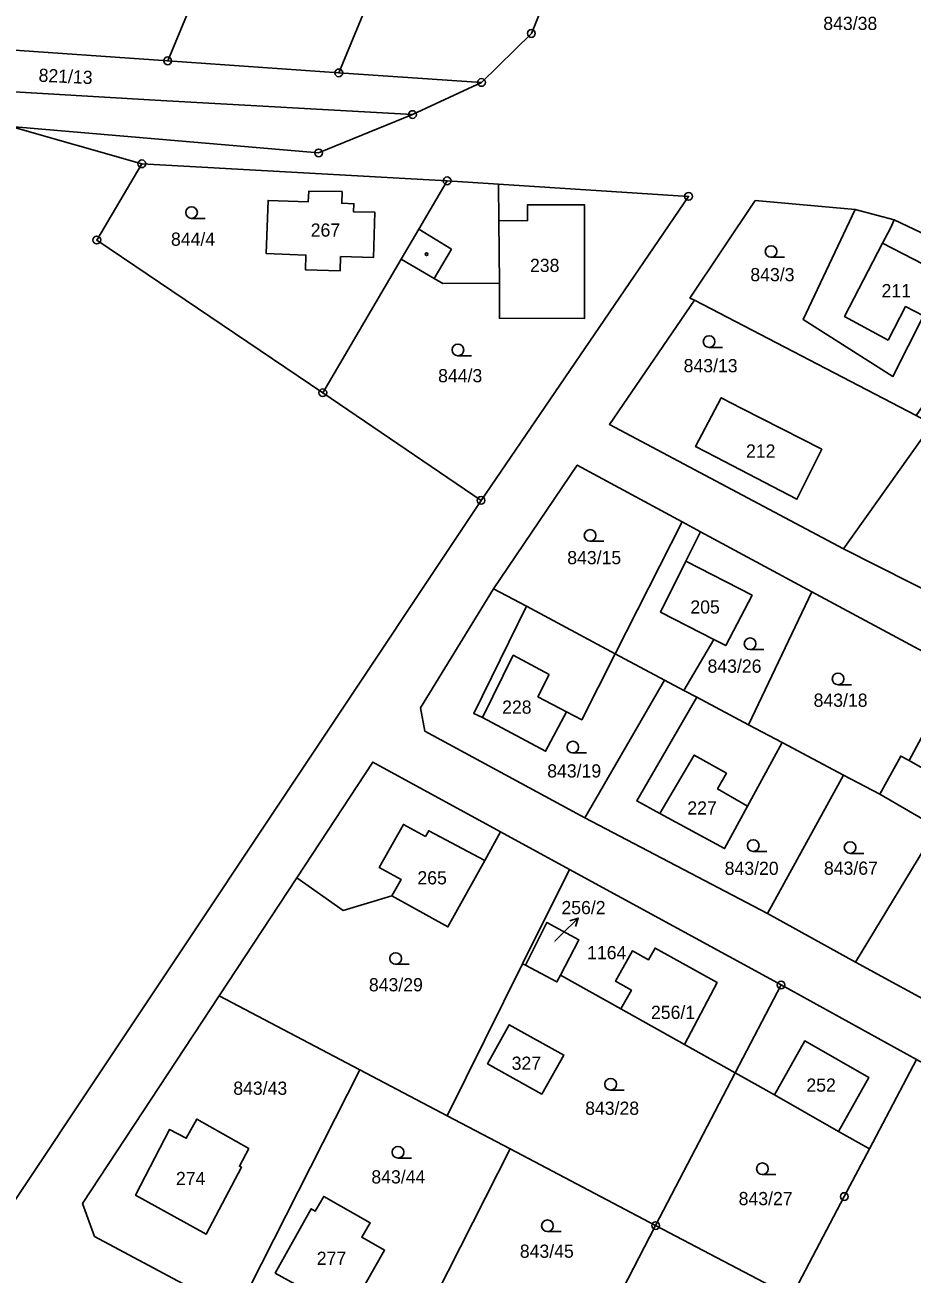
# Model space of a CAD drawing. Extents: x -654083 to -650132, y -1099819 to -1096699.
# Drawn here: x -652566 to -652451.7, y -1098294.4 to -1098133.4 of the extents above; entities that cross this region are included whole.
import ezdxf

# ---------------------------------------------------------------- set-up
doc = ezdxf.new("R2010")
doc.units = 0
for name, color, linetype in [('Geodetické body', 7, 'Continuous'), ('Hranice - vnitř_ kresba', 7, 'Continuous'), ('Obvody jako plochy', 7, 'Continuous'), ('Parcelní čísla', 7, 'Continuous'), ('Prvky pro prodl_ par_ č_', 7, 'Continuous'), ('Značky kultur', 7, 'Continuous'), ('Značky na budově ne v SPI', 7, 'Continuous')]:
    doc.layers.add(name, color=color, linetype=linetype)

msp = doc.modelspace()

# ---------------------------------------------------------------- linework, layer by layer
at = {"layer": 'Geodetické body'}
for centre, radius in [((-652500.78, -1098134.52), 0.5), ((-652500.78, -1098134.52), 0.001), ((-652547.65, -1098138.05), 0.5), ((-652547.65, -1098138.05), 0.001), ((-652525.6, -1098139.6), 0.5), ((-652525.6, -1098139.6), 0.001), ((-652507.21, -1098140.83), 0.5), ((-652507.21, -1098140.83), 0.001), ((-652516.1, -1098144.97), 0.5), ((-652516.1, -1098144.97), 0.001), ((-652550.98, -1098151.31), 0.5), ((-652528.2, -1098149.91), 0.5), ((-652528.2, -1098149.91), 0.001), ((-652550.98, -1098151.31), 0.001), ((-652511.64, -1098153.51), 0.5), ((-652511.64, -1098153.51), 0.001), ((-652480.53, -1098155.51), 0.5), ((-652480.53, -1098155.51), 0.001), ((-652556.79, -1098161.13), 0.5), ((-652556.79, -1098161.13), 0.001), ((-652527.66, -1098180.81), 0.5), ((-652527.66, -1098180.81), 0.001), ((-652507.27, -1098194.68), 0.5), ((-652507.27, -1098194.68), 0.001), ((-652468.6, -1098257.11), 0.5), ((-652468.6, -1098257.11), 0.001), ((-652460.45, -1098284.37), 0.5), ((-652460.45, -1098284.37), 0.001), ((-652484.77, -1098288.11), 0.5), ((-652484.77, -1098288.11), 0.001)]:
    msp.add_circle(centre, radius, dxfattribs=at)
at = {"layer": 'Hranice - vnitř_ kresba'}
for p, q in [((-652504.9, -1098166.67), (-652504.99, -1098158.68)), ((-652511.08, -1098162.29), (-652515.3, -1098159.74)), ((-652455.52, -1098161.54), (-652460.42, -1098170.99)), ((-652513.3, -1098166.11), (-652511.08, -1098162.29)), ((-652454.8, -1098174.04), (-652452.55, -1098169.7)), ((-652452.55, -1098169.7), (-652450.26, -1098170.9)), ((-652460.42, -1098170.99), (-652454.8, -1098174.04)), ((-652480.87, -1098202.52), (-652484.13, -1098209.06)), ((-652484.13, -1098209.06), (-652477.28, -1098212.58)), ((-652507.09, -1098222.64), (-652503.11, -1098214.64)), ((-652503.11, -1098214.64), (-652498.49, -1098217.11)), ((-652498.49, -1098217.11), (-652499.94, -1098219.98)), ((-652496.24, -1098221.91), (-652499.94, -1098219.98)), ((-652484.24, -1098235), (-652479.8, -1098227.5)), ((-652479.8, -1098227.5), (-652475.65, -1098229.83)), ((-652447.46, -1098230.86), (-652452.11, -1098228.21)), ((-652475.65, -1098229.83), (-652476.79, -1098231.86)), ((-652476.79, -1098231.86), (-652472.93, -1098234.09)), ((-652517.27, -1098236.42), (-652520.39, -1098241.96)), ((-652514.44, -1098238), (-652517.27, -1098236.42)), ((-652514.44, -1098238), (-652514.01, -1098237.24)), ((-652514.01, -1098237.24), (-652506.79, -1098241.06)), ((-652520.39, -1098241.96), (-652517.58, -1098243.51)), ((-652518.77, -1098245.61), (-652517.58, -1098243.51)), ((-652469.47, -1098271.27), (-652465.55, -1098264.32)), ((-652465.55, -1098264.32), (-652457.29, -1098269.05)), ((-652457.29, -1098269.05), (-652461.18, -1098275.97))]:
    msp.add_line(p, q, dxfattribs=at)
at = {"layer": 'Obvody jako plochy'}
for points in [[(-652547.65, -1098138.05), (-652531.11, -1098098.13), (-652538.85, -1098095.14), (-652538.06, -1098093.13), (-652551.9, -1098093.63), (-652569.89, -1098136.49)], [(-652511.58, -1098105.71), (-652525.6, -1098139.6), (-652547.65, -1098138.05), (-652531.11, -1098098.13)], [(-652507.21, -1098140.83), (-652500.78, -1098134.52), (-652498.91, -1098129.94), (-652495.32, -1098121.29), (-652492.02, -1098113.3), (-652511.58, -1098105.71), (-652525.6, -1098139.6)], [(-652507.27, -1098194.68), (-652527.66, -1098180.81), (-652556.79, -1098161.13), (-652550.98, -1098151.31), (-652567.88, -1098146.52), (-652571.82, -1098152.16), (-652589.48, -1098177.59), (-652601.2, -1098194.45), (-652613.08, -1098211.55), (-652624.95, -1098228.23), (-652628.47, -1098233.23), (-652636.96, -1098245.34), (-652638.2, -1098247.18), (-652572.57, -1098292.6)], [(-652527.66, -1098180.81), (-652517.57, -1098163.62), (-652515.3, -1098159.74), (-652511.64, -1098153.51), (-652550.98, -1098151.31), (-652556.79, -1098161.13)], [(-652513.3, -1098166.11), (-652517.57, -1098163.62), (-652527.66, -1098180.81), (-652507.27, -1098194.68), (-652480.53, -1098155.51), (-652505.04, -1098153.93), (-652504.99, -1098158.68), (-652501.26, -1098158.62), (-652501.26, -1098156.58), (-652493.93, -1098156.61), (-652493.95, -1098171.25), (-652504.89, -1098171.22), (-652504.9, -1098166.67), (-652512.2, -1098166.75)], [(-652511.64, -1098153.51), (-652505.04, -1098153.93), (-652504.99, -1098158.68), (-652501.26, -1098158.62), (-652501.26, -1098156.58), (-652493.93, -1098156.61), (-652493.95, -1098171.25), (-652504.89, -1098171.22), (-652504.9, -1098166.67), (-652512.2, -1098166.75), (-652513.3, -1098166.11), (-652517.57, -1098163.62), (-652515.3, -1098159.74)], [(-652525.17, -1098154.89), (-652529.46, -1098154.83), (-652529.56, -1098156.23), (-652534.72, -1098156.04), (-652534.98, -1098162.86), (-652529.83, -1098163.07), (-652529.9, -1098164.96), (-652525.41, -1098165.1), (-652525.36, -1098163.26), (-652521.13, -1098163.39), (-652520.95, -1098157.55), (-652523.7, -1098157.52), (-652523.65, -1098156.45), (-652525.21, -1098156.39)], [(-652534.72, -1098156.04), (-652534.98, -1098162.86), (-652529.83, -1098163.07), (-652529.9, -1098164.96), (-652525.41, -1098165.1), (-652525.36, -1098163.26), (-652521.13, -1098163.39), (-652520.95, -1098157.55), (-652523.7, -1098157.52), (-652523.65, -1098156.45), (-652525.21, -1098156.39), (-652525.17, -1098154.89), (-652529.46, -1098154.83), (-652529.56, -1098156.23)], [(-652525.17, -1098154.89), (-652529.46, -1098154.83), (-652529.56, -1098156.23), (-652534.72, -1098156.04), (-652534.98, -1098162.86), (-652529.83, -1098163.07), (-652529.9, -1098164.96), (-652525.41, -1098165.1), (-652525.36, -1098163.26), (-652521.13, -1098163.39), (-652520.95, -1098157.55), (-652523.7, -1098157.52), (-652523.65, -1098156.45), (-652525.21, -1098156.39)], [(-652493.93, -1098156.61), (-652501.26, -1098156.58), (-652501.26, -1098158.62), (-652504.99, -1098158.68), (-652504.9, -1098166.67), (-652504.89, -1098171.22), (-652493.95, -1098171.25)], [(-652447.61, -1098165.63), (-652455.52, -1098161.54), (-652454.51, -1098159.59), (-652454.04, -1098158.52), (-652438.74, -1098165.81), (-652451.18, -1098183.76), (-652479.78, -1098168.86), (-652480.34, -1098168.62), (-652471.94, -1098156.04), (-652459.04, -1098157.21), (-652465.75, -1098171.38), (-652454.19, -1098178.7), (-652450.26, -1098170.9)], [(-652465.75, -1098171.38), (-652459.04, -1098157.21), (-652454.04, -1098158.52), (-652454.51, -1098159.59), (-652455.52, -1098161.54), (-652447.61, -1098165.63), (-652450.26, -1098170.9), (-652454.19, -1098178.7)], [(-652454.8, -1098174.04), (-652452.55, -1098169.7), (-652450.26, -1098170.9), (-652447.61, -1098165.63), (-652455.52, -1098161.54), (-652460.42, -1098170.99)], [(-652479.78, -1098168.86), (-652451.18, -1098183.76), (-652449.12, -1098184.86), (-652460.54, -1098200.94), (-652490.72, -1098184.89)], [(-652476.95, -1098189.12), (-652479.62, -1098187.74), (-652476.32, -1098181.45), (-652473.65, -1098182.82), (-652463.35, -1098188.09), (-652466.56, -1098194.52)], [(-652476.95, -1098189.12), (-652479.62, -1098187.74), (-652476.32, -1098181.45), (-652473.65, -1098182.82), (-652463.35, -1098188.09), (-652466.56, -1098194.52)], [(-652476.32, -1098181.45), (-652473.65, -1098182.82), (-652463.35, -1098188.09), (-652466.56, -1098194.52), (-652476.95, -1098189.12), (-652479.62, -1098187.74)], [(-652429.64, -1098216.72), (-652418.86, -1098201.13), (-652431.25, -1098194.35), (-652437.92, -1098190.67), (-652449.12, -1098184.86), (-652460.54, -1098200.94), (-652447.46, -1098207.53), (-652441.38, -1098195.99), (-652436.88, -1098198.31), (-652431.47, -1098201.1), (-652432.69, -1098203.57), (-652429.99, -1098205.12), (-652433.54, -1098211.53), (-652441.46, -1098207.39), (-652442.8, -1098210.03)], [(-652412.58, -1098234.48), (-652404.85, -1098238.65), (-652405.26, -1098241.23), (-652414.45, -1098256.06), (-652423.45, -1098271.48), (-652447.01, -1098260.7), (-652459, -1098254.16), (-652470.33, -1098247.92), (-652493.88, -1098235.58), (-652514.5, -1098224.43), (-652515.09, -1098221.42), (-652505.66, -1098206.07), (-652494.88, -1098190.13), (-652481.36, -1098197.42), (-652478.97, -1098198.71), (-652464.63, -1098206.44), (-652437.63, -1098220.99), (-652433.22, -1098223.36), (-652419.95, -1098230.51)], [(-652481.36, -1098197.42), (-652489.98, -1098214.43), (-652501.43, -1098208.32), (-652505.66, -1098206.07), (-652494.88, -1098190.13)], [(-652483.61, -1098217.83), (-652481.13, -1098219.15), (-652477.28, -1098212.58), (-652475.73, -1098213.38), (-652472.34, -1098206.9), (-652480.87, -1098202.52), (-652478.97, -1098198.71), (-652481.36, -1098197.42), (-652489.98, -1098214.43)], [(-652478.97, -1098198.71), (-652464.63, -1098206.44), (-652472.82, -1098223.59), (-652479.46, -1098220.04), (-652481.13, -1098219.15), (-652477.28, -1098212.58), (-652475.73, -1098213.38), (-652472.34, -1098206.9), (-652480.87, -1098202.52)], [(-652472.34, -1098206.9), (-652480.87, -1098202.52), (-652484.13, -1098209.06), (-652477.28, -1098212.58), (-652475.73, -1098213.38)], [(-652515.09, -1098221.42), (-652514.5, -1098224.43), (-652493.88, -1098235.58), (-652483.61, -1098217.83), (-652489.98, -1098214.43), (-652494.29, -1098222.93), (-652496.24, -1098221.91), (-652498.95, -1098226.99), (-652507.09, -1098222.64), (-652508.2, -1098222.14), (-652501.43, -1098208.32), (-652505.66, -1098206.07)], [(-652452.11, -1098228.21), (-652453.17, -1098227.62), (-652455.88, -1098232.53), (-652460.56, -1098230.06), (-652468.47, -1098225.89), (-652472.82, -1098223.59), (-652464.63, -1098206.44), (-652437.63, -1098220.99), (-652439.57, -1098224.21), (-652447.75, -1098220.12)], [(-652489.98, -1098214.43), (-652494.29, -1098222.93), (-652496.24, -1098221.91), (-652498.95, -1098226.99), (-652507.09, -1098222.64), (-652508.2, -1098222.14), (-652501.43, -1098208.32)], [(-652498.49, -1098217.11), (-652499.94, -1098219.98), (-652496.24, -1098221.91), (-652498.95, -1098226.99), (-652507.09, -1098222.64), (-652503.11, -1098214.64)], [(-652468.47, -1098225.89), (-652460.56, -1098230.06), (-652470.33, -1098247.92), (-652493.88, -1098235.58), (-652483.61, -1098217.83), (-652481.13, -1098219.15), (-652479.46, -1098220.04), (-652487.21, -1098233.39), (-652484.24, -1098235), (-652475.89, -1098239.53), (-652472.93, -1098234.09)], [(-652472.93, -1098234.09), (-652468.47, -1098225.89), (-652472.82, -1098223.59), (-652479.46, -1098220.04), (-652487.21, -1098233.39), (-652484.24, -1098235), (-652475.89, -1098239.53)], [(-652433.22, -1098223.36), (-652442.8, -1098240.15), (-652448.5, -1098236.83), (-652455.88, -1098232.53), (-652453.17, -1098227.62), (-652452.11, -1098228.21), (-652447.75, -1098220.12), (-652439.57, -1098224.21), (-652437.63, -1098220.99)], [(-652439.57, -1098224.21), (-652447.75, -1098220.12), (-652452.11, -1098228.21), (-652447.46, -1098230.86), (-652445.88, -1098228.13), (-652442.61, -1098229.97)], [(-652475.89, -1098239.53), (-652472.93, -1098234.09), (-652476.79, -1098231.86), (-652475.65, -1098229.83), (-652479.8, -1098227.5), (-652484.24, -1098235)], [(-652452.25, -1098320.64), (-652453.03, -1098320.31), (-652482.82, -1098329.7), (-652501.09, -1098319.77), (-652519.51, -1098309.76), (-652538.73, -1098299.32), (-652557.1, -1098289.51), (-652558.61, -1098285.27), (-652541.02, -1098258.51), (-652531.03, -1098243.32), (-652521.22, -1098228.39), (-652504.75, -1098237.38), (-652495.89, -1098242.22), (-652468.6, -1098257.11), (-652451.14, -1098266.7), (-652429.53, -1098278.59), (-652428.62, -1098280.65), (-652437.69, -1098297.44)], [(-652521.22, -1098228.39), (-652504.75, -1098237.38), (-652506.79, -1098241.06), (-652511.54, -1098249.63), (-652518.77, -1098245.61), (-652525.03, -1098247.5), (-652531.03, -1098243.32)], [(-652459, -1098254.16), (-652448.5, -1098236.83), (-652455.88, -1098232.53), (-652460.56, -1098230.06), (-652470.33, -1098247.92)], [(-652531.03, -1098243.32), (-652541.02, -1098258.51), (-652522.9, -1098268.04), (-652511.62, -1098273.98), (-652501.91, -1098254.37), (-652495.89, -1098242.22), (-652504.75, -1098237.38), (-652506.79, -1098241.06), (-652511.54, -1098249.63), (-652518.77, -1098245.61), (-652525.03, -1098247.5)], [(-652514.44, -1098238), (-652514.01, -1098237.24), (-652506.79, -1098241.06), (-652511.54, -1098249.63), (-652518.77, -1098245.61), (-652517.58, -1098243.51), (-652520.39, -1098241.96), (-652517.27, -1098236.42)], [(-652414.45, -1098256.06), (-652442.8, -1098240.15), (-652448.5, -1098236.83), (-652459, -1098254.16), (-652447.01, -1098260.7), (-652423.45, -1098271.48)], [(-652485.7, -1098253.88), (-652484.84, -1098252.35), (-652476.85, -1098256.8), (-652481.06, -1098264.76), (-652474.5, -1098268.42), (-652468.6, -1098257.11), (-652495.89, -1098242.22), (-652501.91, -1098254.37), (-652501.55, -1098254.56), (-652498.78, -1098249.05), (-652494.68, -1098251.28), (-652497.03, -1098255.85), (-652489.24, -1098260.19), (-652487.89, -1098257.78), (-652489.93, -1098256.62), (-652487.75, -1098252.72)], [(-652497.03, -1098255.85), (-652497.48, -1098256.72), (-652501.55, -1098254.56), (-652498.78, -1098249.05), (-652494.68, -1098251.28)], [(-652494.68, -1098251.28), (-652498.78, -1098249.05), (-652501.55, -1098254.56), (-652497.48, -1098256.72), (-652497.03, -1098255.85)], [(-652484.84, -1098252.35), (-652476.85, -1098256.8), (-652481.06, -1098264.76), (-652489.24, -1098260.19), (-652487.89, -1098257.78), (-652489.93, -1098256.62), (-652487.75, -1098252.72), (-652485.7, -1098253.88)], [(-652489.93, -1098256.62), (-652487.89, -1098257.78), (-652489.24, -1098260.19), (-652481.06, -1098264.76), (-652476.85, -1098256.8), (-652484.84, -1098252.35), (-652485.7, -1098253.88), (-652487.75, -1098252.72)], [(-652489.24, -1098260.19), (-652497.03, -1098255.85), (-652497.48, -1098256.72), (-652501.55, -1098254.56), (-652501.91, -1098254.37), (-652511.62, -1098273.98), (-652503.52, -1098278.24), (-652484.77, -1098288.11), (-652474.5, -1098268.42), (-652481.06, -1098264.76)], [(-652468.6, -1098257.11), (-652451.14, -1098266.7), (-652457.21, -1098278.22), (-652461.18, -1098275.97), (-652469.47, -1098271.27), (-652474.5, -1098268.42)], [(-652522.9, -1098268.04), (-652538.73, -1098299.32), (-652557.1, -1098289.51), (-652558.61, -1098285.27), (-652541.02, -1098258.51)], [(-652506.44, -1098267.27), (-652503.63, -1098262.23), (-652496.61, -1098266.15), (-652499.44, -1098271.17)], [(-652496.61, -1098266.15), (-652499.44, -1098271.17), (-652506.44, -1098267.27), (-652503.63, -1098262.23)], [(-652503.63, -1098262.23), (-652496.61, -1098266.15), (-652499.44, -1098271.17), (-652506.44, -1098267.27)], [(-652461.18, -1098275.97), (-652469.47, -1098271.27), (-652465.55, -1098264.32), (-652457.29, -1098269.05)], [(-652428.62, -1098280.65), (-652437.69, -1098297.44), (-652452.25, -1098320.64), (-652453.03, -1098320.31), (-652466.48, -1098314.63), (-652474.83, -1098311.1), (-652467.26, -1098297.29), (-652460.45, -1098284.37), (-652457.21, -1098278.22), (-652451.14, -1098266.7), (-652429.53, -1098278.59)], [(-652538.73, -1098299.32), (-652519.51, -1098309.76), (-652503.52, -1098278.24), (-652511.62, -1098273.98), (-652522.9, -1098268.04)], [(-652469.47, -1098271.27), (-652474.5, -1098268.42), (-652484.77, -1098288.11), (-652467.26, -1098297.29), (-652460.45, -1098284.37), (-652457.21, -1098278.22), (-652461.18, -1098275.97)], [(-652542.71, -1098289.23), (-652538.13, -1098280.6), (-652538.4, -1098280.46), (-652537.21, -1098278.18), (-652543.9, -1098274.39), (-652545.25, -1098276.86), (-652547.4, -1098275.73), (-652551.79, -1098284.21)], [(-652547.4, -1098275.73), (-652545.25, -1098276.86), (-652543.9, -1098274.39), (-652537.21, -1098278.18), (-652538.4, -1098280.46), (-652538.13, -1098280.6), (-652542.71, -1098289.23), (-652551.79, -1098284.21)], [(-652538.4, -1098280.46), (-652538.13, -1098280.6), (-652542.71, -1098289.23), (-652551.79, -1098284.21), (-652547.4, -1098275.73), (-652545.25, -1098276.86), (-652543.9, -1098274.39), (-652537.21, -1098278.18)], [(-652484.77, -1098288.11), (-652503.52, -1098278.24), (-652519.51, -1098309.76), (-652501.09, -1098319.77)], [(-652533.78, -1098294.23), (-652529.16, -1098285.95), (-652528.64, -1098286.25), (-652527.53, -1098284.35), (-652521.54, -1098287.77), (-652522.65, -1098289.62), (-652519.7, -1098291.26), (-652524.36, -1098299.45)], [(-652519.7, -1098291.26), (-652524.36, -1098299.45), (-652533.78, -1098294.23), (-652529.16, -1098285.95), (-652528.64, -1098286.25), (-652527.53, -1098284.35), (-652521.54, -1098287.77), (-652522.65, -1098289.62)], [(-652527.53, -1098284.35), (-652521.54, -1098287.77), (-652522.65, -1098289.62), (-652519.7, -1098291.26), (-652524.36, -1098299.45), (-652533.78, -1098294.23), (-652529.16, -1098285.95), (-652528.64, -1098286.25)], [(-652474.83, -1098311.1), (-652467.26, -1098297.29), (-652484.77, -1098288.11), (-652501.09, -1098319.77), (-652482.82, -1098329.7), (-652469.79, -1098320.58), (-652466.48, -1098314.63)]]:
    msp.add_lwpolyline(points, close=True, dxfattribs=at)
for points in [[(-652450.84, -1098332.97), (-652463.05, -1098328.79), (-652482.03, -1098339.62), (-652508.1, -1098348.73), (-652518.45, -1098354.28), (-652546.92, -1098343), (-652545.7, -1098345.51), (-652569.6, -1098331.43), (-652594.11, -1098323.43), (-652572.57, -1098292.6), (-652507.27, -1098194.68), (-652480.53, -1098155.51), (-652505.04, -1098153.93), (-652511.64, -1098153.51), (-652550.98, -1098151.31), (-652567.88, -1098146.52), (-652528.2, -1098149.91), (-652516.1, -1098144.97), (-652507.21, -1098140.83), (-652500.78, -1098134.52), (-652498.91, -1098129.94)], [(-652686.79, -1098136.97), (-652656.36, -1098138.38), (-652587.67, -1098144.11), (-652567.88, -1098146.52), (-652528.2, -1098149.91), (-652516.1, -1098144.97), (-652548.55, -1098143.17), (-652571.08, -1098141.82), (-652597.99, -1098140.29), (-652602.95, -1098136.12), (-652601.9, -1098131.24)], [(-652601.9, -1098131.24), (-652602.95, -1098136.12), (-652597.99, -1098140.29), (-652571.08, -1098141.82), (-652548.55, -1098143.17), (-652516.1, -1098144.97), (-652507.21, -1098140.83), (-652525.6, -1098139.6), (-652547.65, -1098138.05), (-652569.89, -1098136.49), (-652596.06, -1098134.52), (-652596.03, -1098130.4)], [(-652438.74, -1098165.81), (-652454.04, -1098158.52), (-652459.04, -1098157.21), (-652471.94, -1098156.04), (-652480.34, -1098168.62), (-652479.78, -1098168.86), (-652490.72, -1098184.89), (-652460.54, -1098200.94), (-652447.46, -1098207.53)]]:
    msp.add_lwpolyline(points, dxfattribs=at)
at = {"layer": 'Prvky pro prodl_ par_ č_'}
for p, q in [((-652496.88, -1098250.62), (-652494.76, -1098248.5)), ((-652497.74, -1098251.48), (-652496.88, -1098250.62))]:
    msp.add_line(p, q, dxfattribs=at)
msp.add_lwpolyline([(-652495.82, -1098248.85), (-652494.76, -1098248.5), (-652495.11, -1098249.56)], dxfattribs=at)
at = {"layer": 'Značky kultur'}
for p, q in [((-652542.83, -1098158.34), (-652544.58, -1098158.34)), ((-652468.14, -1098163.36), (-652469.89, -1098163.36)), ((-652476.13, -1098174.97), (-652477.88, -1098174.97)), ((-652508.5, -1098176.04), (-652510.25, -1098176.04)), ((-652491.46, -1098199.94), (-652493.21, -1098199.94)), ((-652470.84, -1098213.9), (-652472.59, -1098213.9)), ((-652459.51, -1098218.43), (-652461.26, -1098218.43)), ((-652493.69, -1098227.21), (-652495.44, -1098227.21)), ((-652470.44, -1098239.9), (-652472.19, -1098239.9)), ((-652457.95, -1098240.15), (-652459.7, -1098240.15)), ((-652516.52, -1098254.45), (-652518.27, -1098254.45)), ((-652488.81, -1098270.65), (-652490.56, -1098270.65)), ((-652516.22, -1098279.41), (-652517.97, -1098279.41)), ((-652469.26, -1098281.54), (-652471.01, -1098281.54)), ((-652496.96, -1098288.88), (-652498.71, -1098288.88))]:
    msp.add_line(p, q, dxfattribs=at)
for centre in [(-652544.58, -1098157.59), (-652469.89, -1098162.61), (-652477.88, -1098174.22), (-652510.25, -1098175.29), (-652493.21, -1098199.19), (-652472.59, -1098213.15), (-652461.26, -1098217.68), (-652495.44, -1098226.46), (-652472.19, -1098239.15), (-652459.7, -1098239.4), (-652518.27, -1098253.7), (-652490.56, -1098269.9), (-652517.97, -1098278.66), (-652471.01, -1098280.79), (-652498.71, -1098288.13)]:
    msp.add_circle(centre, 0.75, dxfattribs=at)
at = {"layer": 'Značky na budově ne v SPI'}
msp.add_circle((-652514.28, -1098162.96), 0.175, dxfattribs=at)

# ---------------------------------------------------------------- texts
at = {"layer": 'Parcelní čísla'}
for s, p in [('843/38', (-652463.16, -1098134.07)), ('267', (-652529.22, -1098160.7)), ('844/4', (-652547.23, -1098161.87)), ('238', (-652500.96, -1098165.25)), ('843/3', (-652472.56, -1098166.44)), ('211', (-652455.65, -1098168.51)), ('843/13', (-652481.16, -1098178.17)), ('844/3', (-652512.8, -1098179.46)), ('212', (-652473.12, -1098189.17)), ('843/15', (-652496.16, -1098202.9)), ('205', (-652480.29, -1098209.26)), ('843/26', (-652478.08, -1098216.88)), ('843/18', (-652464.41, -1098221.27)), ('228', (-652504.55, -1098222.16)), ('843/19', (-652498.74, -1098230.38)), ('227', (-652480.68, -1098235.15)), ('265', (-652515.47, -1098244.15)), ('843/20', (-652475.87, -1098242.93)), ('843/67', (-652463.08, -1098242.91)), ('1164', (-652493.6, -1098253.79)), ('843/29', (-652521.72, -1098257.93)), ('256/1', (-652485.37, -1098261.49)), ('327', (-652503.32, -1098268.04)), ('843/43', (-652539.2, -1098271.26)), ('252', (-652465.34, -1098270.86)), ('843/28', (-652493.85, -1098273.84)), ('274', (-652546.59, -1098282.89)), ('843/44', (-652521.4, -1098282.68)), ('843/27', (-652474.07, -1098285.48)), ('843/45', (-652502.27, -1098292.26)), ('277', (-652528.44, -1098293.17))]:
    msp.add_text(s, height=1.7, dxfattribs=at).set_placement(p)
for s, height, rotation, p in [('821/13', 1.7, 357.345, (-652564.32, -1098140.73)), ('256/2', 0.1, 63.342, (-652497.82, -1098251.65))]:
    msp.add_text(s, height=height, rotation=rotation, dxfattribs=at).set_placement(p)
at = {"layer": 'Prvky pro prodl_ par_ č_'}
msp.add_text('256/2', height=1.7, dxfattribs=at).set_placement((-652496.91, -1098247.99))

doc.saveas('drawing.dxf')
